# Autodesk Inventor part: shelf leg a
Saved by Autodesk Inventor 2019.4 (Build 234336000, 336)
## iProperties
Created: 2020-09
Part Number: shelf leg a
Material: Generic
Document SubType Name: Modeling
Designer: Administrator
Density: 1 g/cm^3
Appearance: Default
Title: shelf leg a
Author: Administrator
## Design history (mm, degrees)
feature "Body1"
body "Solid1"
